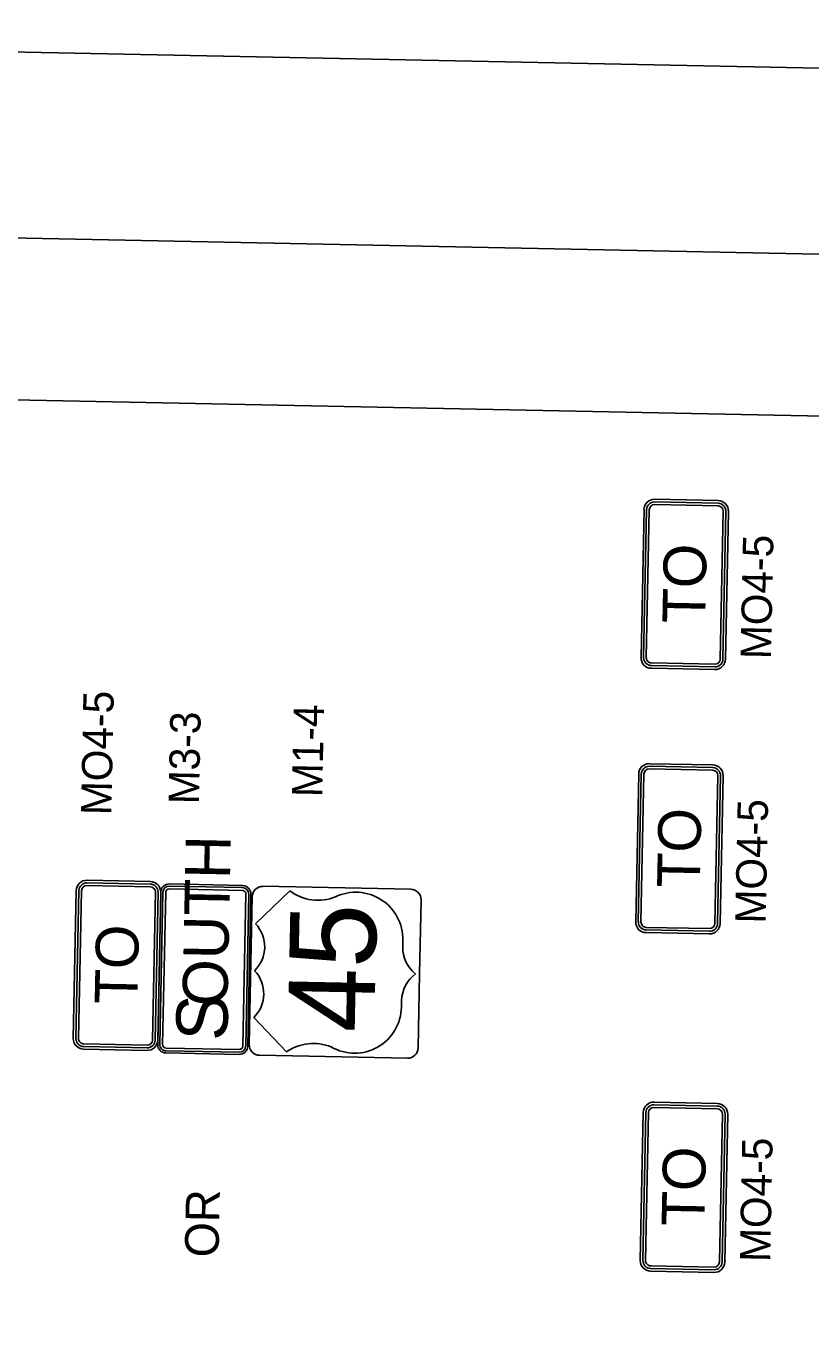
# Model space of a CAD drawing. Extents: x 345549 to 379569, y 127949 to 230467.
# Drawn here: x 353466 to 357645, y 223488 to 230467 of the extents above; entities that cross this region are included whole.
import ezdxf

# ---------------------------------------------------------------- set-up
doc = ezdxf.new("R2010")
doc.units = 0
for name, color, linetype in [('CA-TEXT', 7, 'Continuous'), ('P_RDWY_Text', 7, 'Continuous'), ('P_SGN_Cell', 7, 'Continuous'), ('PLT_Sheet_Border', 7, 'Continuous'), ('PLT_Sheet_Info', 7, 'Continuous')]:
    doc.layers.add(name, color=color, linetype=linetype)

msp = doc.modelspace()

# ---------------------------------------------------------------- linework, layer by layer
at = {"layer": 'P_RDWY_Text'}
msp.add_lwpolyline([(345549, 179477.5), (346575.9, 230467.1), (379569.2, 229802.6), (378542.3, 178813)], close=True, dxfattribs=at)
at = {"layer": 'P_SGN_Cell'}
for p, q in [((354166.5, 225044.5), (354182.9, 225855)), ((354177.8, 225044.9), (354194.1, 225854.8)), ((354192.8, 225044.6), (354209.1, 225854.5)), ((354228.2, 225872.8), (354618.1, 225865)), ((354228.5, 225887.8), (354618.4, 225880)), ((354228.8, 225899.1), (354618.7, 225891.2)), ((354870.1, 225862.4), (354688, 225687.5)), ((354727.3, 225886.7), (355514.6, 225870.8)), ((354636.5, 225845.8), (354620.2, 225036)), ((354651.5, 225845.5), (354635.2, 225035.7)), ((354662.8, 225845.3), (354646.4, 225035.5)), ((354654, 225044.2), (354669.9, 225831.6)), ((355569.7, 225813.4), (355561.8, 225419.8)), ((355569.7, 225813.4), (355569.7, 225813.4)), ((355471.4, 225564.5), (355472.2, 225600.2)), ((355561.8, 225419.8), (355553.9, 225026.1)), ((355465, 225243.1), (355465.7, 225278.8)), ((354677.9, 225187.5), (354852.8, 225005.3)), ((354211.2, 225025.5), (354601.1, 225017.6)), ((354210.6, 224999.2), (354600.5, 224991.4)), ((354210.9, 225010.5), (354600.8, 225002.6)), ((355496.5, 224971), (354709.1, 224986.9))]:
    msp.add_line(p, q, dxfattribs=at)
for points in [[(357151.5, 227940.9), (356814, 227947.7)], [(356756.7, 227892.6), (356740.8, 227105.2)], [(356770.7, 227892.3), (356754.9, 227105)], [(356784.8, 227892), (356768.9, 227104.7)], [(357150.9, 227912.8), (356813.5, 227919.6)], [(357151.2, 227926.8), (356813.7, 227933.6)], [(357162.6, 227096.7), (357178.5, 227884.1)], [(357176.7, 227096.5), (357192.5, 227883.8)], [(357190.7, 227096.2), (357206.6, 227883.5)], [(356795.9, 227047.9), (357133.3, 227041.1)], [(356796.2, 227061.9), (357133.6, 227055.1)], [(356796.5, 227076), (357133.9, 227069.2)], [(356728.3, 226484.7), (356712.4, 225697.4)], [(356742.4, 226484.5), (356726.5, 225697.1)], [(356756.4, 226484.2), (356740.6, 225696.8)], [(357122.5, 226504.9), (356785.1, 226511.7)], [(357122.8, 226519), (356785.4, 226525.8)], [(357123.1, 226533.1), (356785.7, 226539.8)], [(357134.2, 225688.9), (357150.1, 226476.2)], [(357148.3, 225688.6), (357164.2, 226476)], [(357162.4, 225688.3), (357178.2, 226475.7)], [(353732.9, 225864), (353717.1, 225076.7)], [(353747, 225863.8), (353731.2, 225076.4)], [(353761.1, 225863.5), (353745.2, 225076.1)], [(354127.2, 225884.2), (353789.7, 225891)], [(354127.5, 225898.3), (353790, 225905.1)], [(354127.7, 225912.4), (353790.3, 225919.1)], [(354138.9, 225068.2), (354154.7, 225855.5)], [(354152.9, 225067.9), (354168.8, 225855.3)], [(354167, 225067.6), (354182.9, 225855)], [(356767.8, 225654.1), (357105.3, 225647.3)], [(356768.1, 225668.2), (357105.5, 225661.4)], [(356767.5, 225640), (357105, 225633.2)], [(353772.2, 225019.3), (354109.6, 225012.5)], [(353772.5, 225033.4), (354109.9, 225026.6)], [(353772.8, 225047.5), (354110.2, 225040.7)], [(357147.4, 224730.4), (356810, 224737.2)], [(356752.6, 224682.1), (356736.7, 223894.8)], [(356766.7, 224681.8), (356750.8, 223894.5)], [(356780.7, 224681.5), (356764.9, 223894.2)], [(357146.8, 224702.3), (356809.4, 224709.1)], [(357147.1, 224716.3), (356809.7, 224723.1)], [(357158.5, 223886.3), (357174.4, 224673.6)], [(357172.6, 223886), (357188.5, 224673.3)], [(357186.7, 223885.7), (357202.5, 224673)], [(356791.8, 223837.4), (357129.3, 223830.6)], [(356792.1, 223851.4), (357129.6, 223844.6)], [(356792.4, 223865.5), (357129.8, 223858.7)]]:
    msp.add_lwpolyline(points, dxfattribs=at)
for centre, radius, start, end in [((356812.9, 227891.4), 56.3, 88.84622, 178.84622), ((356812.9, 227891.4), 42.2, 88.84622, 178.84622), ((356812.9, 227891.4), 28.1, 88.84622, 178.84622), ((357150.3, 227884.6), 28.1, 358.84622, 88.84622), ((357150.3, 227884.6), 42.2, 358.84622, 88.84622), ((357150.3, 227884.6), 56.3, 358.84622, 88.84622), ((356797, 227104.1), 56.3, 178.84622, 268.84622), ((356797, 227104.1), 42.2, 178.84622, 268.84622), ((356797, 227104.1), 28.1, 178.84622, 268.84622), ((357134.5, 227097.3), 56.3, 268.84622, 358.84622), ((357134.5, 227097.3), 42.2, 268.84622, 358.84622), ((357134.5, 227097.3), 28.1, 268.84622, 358.84622), ((356784.6, 226483.6), 56.3, 88.84622, 178.84622), ((356784.6, 226483.6), 42.2, 88.84622, 178.84622), ((356784.6, 226483.6), 28.1, 88.84622, 178.84622), ((357122, 226476.8), 28.1, 358.84622, 88.84622), ((357122, 226476.8), 42.2, 358.84622, 88.84622), ((357122, 226476.8), 56.3, 358.84622, 88.84622), ((353789.2, 225862.9), 56.3, 88.84622, 178.84622), ((353789.2, 225862.9), 42.2, 88.84622, 178.84622), ((353789.2, 225862.9), 28.1, 88.84622, 178.84622), ((354126.6, 225856.1), 28.1, 358.84622, 88.84622), ((354126.6, 225856.1), 42.2, 358.84622, 88.84622), ((354126.6, 225856.1), 56.3, 358.84622, 88.84622), ((354227.8, 225854.1), 45, 88.84622, 178.84622), ((354227.8, 225854.1), 33.7, 88.84622, 178.84622), ((354227.8, 225854.1), 18.7, 88.84622, 178.84622), ((354617.8, 225846.2), 18.7, 358.84622, 88.84622), ((354617.8, 225846.2), 33.7, 358.84622, 88.84622), ((354617.8, 225846.2), 45, 358.84622, 88.84622), ((354726.1, 225830.4), 56.2, 88.84622, 178.84622), ((355020.2, 226062.4), 250, 233.11428, 291.9873), ((355222.2, 225605.2), 250, 358.84616, 115.69277), ((355513.5, 225814.6), 56.2, 358.84622, 88.84622), ((354557.9, 225565), 178.6, 314.41906, 43.27339), ((356768.7, 225696.3), 56.3, 178.84622, 268.84622), ((356768.7, 225696.3), 42.2, 178.84622, 268.84622), ((356768.7, 225696.3), 28.1, 178.84622, 268.84622), ((357106.1, 225689.5), 56.3, 268.84622, 358.84622), ((357106.1, 225689.5), 42.2, 268.84622, 358.84622), ((357106.1, 225689.5), 28.1, 268.84622, 358.84622), ((355652.2, 225561.9), 180.8, 179.18852, 231.63404), ((354552.9, 225315), 178.6, 314.41906, 43.27339), ((355646.4, 225274.1), 180.8, 126.05841, 178.50393), ((355215, 225248.1), 250, 240.09813, 358.84629), ((353773.3, 225075.6), 56.3, 178.84622, 268.84622), ((353773.3, 225075.6), 42.2, 178.84622, 268.84622), ((353773.3, 225075.6), 28.1, 178.84622, 268.84622), ((354110.8, 225068.8), 56.3, 268.84622, 358.84622), ((354110.8, 225068.8), 42.2, 268.84622, 358.84622), ((354110.8, 225068.8), 28.1, 268.84622, 358.84622), ((354211.5, 225044.2), 45, 179.61188, 268.84622), ((354211.5, 225044.2), 33.7, 178.84622, 268.84622), ((354211.5, 225044.2), 18.7, 178.84622, 268.84622), ((354601.4, 225036.4), 45, 268.84622, 358.84622), ((354601.4, 225036.4), 33.7, 268.84622, 358.84622), ((354601.4, 225036.4), 18.7, 268.84622, 358.84622), ((354710.3, 225043.1), 56.2, 178.84622, 268.84622), ((354995.5, 224800), 250, 67.71592, 124.79823), ((355497.6, 225027.2), 56.2, 268.84622, 358.84622), ((356808.9, 224681), 56.3, 88.84622, 178.84622), ((356808.9, 224681), 42.2, 88.84622, 178.84622), ((356808.9, 224681), 28.1, 88.84622, 178.84622), ((357146.3, 224674.2), 28.1, 358.84622, 88.84622), ((357146.3, 224674.2), 42.2, 358.84622, 88.84622), ((357146.3, 224674.2), 56.3, 358.84622, 88.84622), ((356793, 223893.6), 56.3, 178.84622, 268.84622), ((356793, 223893.6), 42.2, 178.84622, 268.84622), ((356793, 223893.6), 28.1, 178.84622, 268.84622), ((357130.4, 223886.8), 56.3, 268.84622, 358.84622), ((357130.4, 223886.8), 42.2, 268.84622, 358.84622), ((357130.4, 223886.8), 28.1, 268.84622, 358.84622)]:
    msp.add_arc(centre, radius, start, end, dxfattribs=at)
at = {"layer": 'PLT_Sheet_Border'}
for points in [[(378542.3, 178813), (379569.2, 229802.6), (346575.9, 230467.1), (345549, 179477.5)], [(377799.7, 179188), (378799.5, 228827.9), (347305.8, 229462.2), (346306.1, 179822.3)]]:
    msp.add_lwpolyline(points, close=True, dxfattribs=at)
at = {"layer": 'PLT_Sheet_Info'}
msp.add_line((378032.2, 227980.7), (348038.3, 228584.8), dxfattribs=at)

# ---------------------------------------------------------------- texts
at = {"layer": 'CA-TEXT'}
msp.add_text('OR', height=180, rotation=88.84682, dxfattribs=at).set_placement((354490.8, 223909.4))
at = {"layer": 'P_SGN_Cell'}
for s, height, p in [('MO4-5', 162, (357432.8, 227095.3)), ('TO', 228, (357082.3, 227285.7)), ('MO4-5', 162, (353919.8, 226264.4)), ('M1-4', 162, (355043, 226360.4)), ('M3-3', 162, (354386.2, 226322.5)), ('TO', 228, (357053.9, 225877.9)), ('MO4-5', 162, (357404.4, 225687.4)), ('OUTH', 240, (354538.1, 225246.3)), ('45', 460, (355319.8, 225106.3)), ('TO', 228, (354058.6, 225257.2)), ('S', 274.3, (354537.8, 225062.5)), ('MO4-5', 162, (357428.7, 223884.8)), ('TO', 228, (357078.2, 224075.3))]:
    msp.add_text(s, height=height, rotation=88.84622, dxfattribs=at).set_placement(p)

doc.saveas('drawing.dxf')
